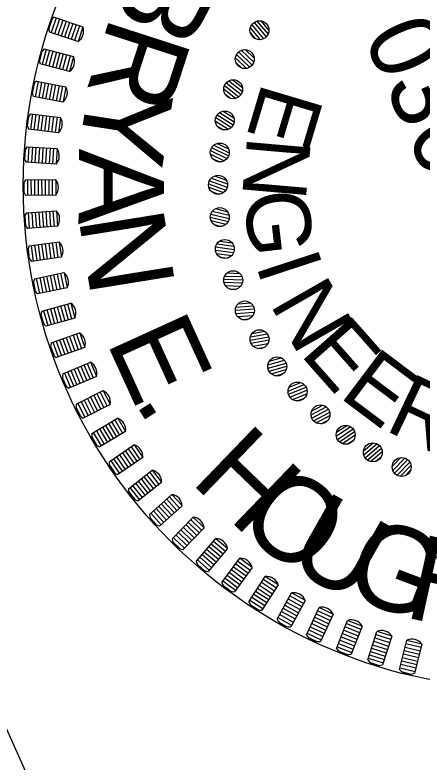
# Model space of a CAD drawing. Extents: x 885268 to 886953, y 552794 to 554777.
# Drawn here: x 886789.1 to 886819.5, y 553213.9 to 553269.8 of the extents above; entities that cross this region are included whole.
import ezdxf

# ---------------------------------------------------------------- set-up
doc = ezdxf.new("R2010")
doc.units = 0
doc.layers.add('Sheet PE Seal Cell', color=7, linetype='Continuous')
doc.layers.add('Sheet Plan CELL', color=7, linetype='Continuous')

msp = doc.modelspace()

# ---------------------------------------------------------------- linework, layer by layer
at = {"layer": 'Sheet PE Seal Cell'}
for p, q in [((886792.129, 553269.585), (886791.758, 553268.483)), ((886791.999, 553269.629), (886794.129, 553268.911)), ((886791.805, 553269.454), (886791.579, 553268.783)), ((886792.38, 553269.5), (886792.009, 553268.398)), ((886792.632, 553269.416), (886792.26, 553268.314)), ((886792.883, 553269.331), (886792.512, 553268.229)), ((886793.135, 553269.246), (886792.763, 553268.144)), ((886793.386, 553269.162), (886793.015, 553268.06)), ((886793.638, 553269.077), (886793.266, 553267.975)), ((886793.889, 553268.992), (886793.518, 553267.89)), ((886806.764, 553269.074), (886807.647, 553268.022)), ((886806.932, 553269.241), (886807.84, 553268.159)), ((886807.153, 553269.345), (886807.981, 553268.358)), ((886807.447, 553269.362), (886808.049, 553268.645)), ((886793.758, 553267.809), (886791.628, 553268.527)), ((886794.136, 553268.894), (886793.774, 553267.819)), ((886806.653, 553268.837), (886807.395, 553267.954)), ((886806.659, 553268.463), (886807.027, 553268.024)), ((886791.066, 553267.076), (886790.885, 553266.392)), ((886791.381, 553267.228), (886791.083, 553266.104)), ((886791.248, 553267.263), (886793.421, 553266.688)), ((886791.637, 553267.16), (886791.34, 553266.036)), ((886791.894, 553267.092), (886791.596, 553265.968)), ((886792.15, 553267.024), (886791.853, 553265.9)), ((886792.407, 553266.957), (886792.109, 553265.832)), ((886792.663, 553266.889), (886792.366, 553265.765)), ((886792.92, 553266.821), (886792.622, 553265.697)), ((886793.176, 553266.753), (886792.879, 553265.629)), ((886805.625, 553266.853), (886806.613, 553265.899)), ((886805.775, 553267.037), (886806.791, 553266.056)), ((886805.984, 553267.163), (886806.911, 553266.269)), ((886806.275, 553267.211), (886806.948, 553266.562)), ((886793.429, 553266.671), (886793.139, 553265.575)), ((886805.54, 553266.606), (886806.37, 553265.805)), ((886805.585, 553266.235), (886805.997, 553265.837)), ((886793.124, 553265.564), (886790.951, 553266.139)), ((886790.486, 553264.655), (886790.35, 553263.959)), ((886790.79, 553264.827), (886790.567, 553263.685)), ((886790.655, 553264.853), (886792.862, 553264.423)), ((886791.05, 553264.776), (886790.828, 553263.635)), ((886791.311, 553264.725), (886791.088, 553263.584)), ((886791.571, 553264.674), (886791.349, 553263.533)), ((886791.832, 553264.624), (886791.609, 553263.482)), ((886792.092, 553264.573), (886791.87, 553263.432)), ((886792.353, 553264.522), (886792.13, 553263.381)), ((886804.725, 553264.526), (886805.807, 553263.68)), ((886804.855, 553264.724), (886805.968, 553263.854)), ((886805.049, 553264.872), (886806.064, 553264.079)), ((886805.334, 553264.949), (886806.071, 553264.374)), ((886792.613, 553264.471), (886792.39, 553263.33)), ((886792.871, 553264.406), (886792.654, 553263.293)), ((886804.666, 553264.272), (886805.575, 553263.562)), ((886792.639, 553263.281), (886790.433, 553263.712)), ((886804.75, 553263.906), (886805.201, 553263.554)), ((886790.359, 553262.392), (886790.213, 553261.238)), ((886790.223, 553262.409), (886792.454, 553262.125)), ((886790.622, 553262.358), (886790.476, 553261.205)), ((886790.886, 553262.325), (886790.739, 553261.171)), ((886791.149, 553262.291), (886791.002, 553261.138)), ((886791.412, 553262.258), (886791.266, 553261.104)), ((886804.181, 553262.328), (886805.379, 553261.579)), ((886804.359, 553262.495), (886805.452, 553261.813)), ((886804.634, 553262.602), (886805.427, 553262.107)), ((886790.067, 553262.2), (886789.978, 553261.497)), ((886791.675, 553262.224), (886791.529, 553261.071)), ((886791.939, 553262.191), (886791.792, 553261.037)), ((886792.202, 553262.157), (886792.055, 553261.004)), ((886792.463, 553262.11), (886792.32, 553260.985)), ((886804.041, 553261.858), (886805.019, 553261.247)), ((886804.072, 553262.117), (886805.238, 553261.389)), ((886792.307, 553260.972), (886790.077, 553261.255)), ((886804.162, 553261.504), (886804.647, 553261.201)), ((886803.921, 553260.059), (886805.079, 553259.495)), ((886804.183, 553260.194), (886805.024, 553259.785)), ((886789.812, 553259.723), (886789.769, 553259.016)), ((886789.954, 553259.942), (886792.198, 553259.806)), ((886790.09, 553259.933), (886790.02, 553258.773)), ((886790.355, 553259.917), (886790.285, 553258.757)), ((886790.62, 553259.901), (886790.55, 553258.741)), ((886790.885, 553259.885), (886790.815, 553258.725)), ((886791.15, 553259.869), (886791.08, 553258.709)), ((886791.415, 553259.853), (886791.345, 553258.693)), ((886791.68, 553259.837), (886791.61, 553258.677)), ((886791.945, 553259.821), (886791.874, 553258.661)), ((886792.209, 553259.791), (886792.14, 553258.659)), ((886803.676, 553259.653), (886804.91, 553259.051)), ((886803.762, 553259.874), (886805.032, 553259.255)), ((886803.671, 553259.392), (886804.708, 553258.887)), ((886803.829, 553259.053), (886804.343, 553258.802)), ((886792.128, 553258.645), (886789.884, 553258.781)), ((886789.721, 553257.234), (886789.725, 553256.526)), ((886789.848, 553257.462), (886792.096, 553257.475)), ((886789.985, 553257.463), (886789.991, 553256.3)), ((886790.25, 553257.464), (886790.257, 553256.301)), ((886790.515, 553257.466), (886790.522, 553256.303)), ((886790.781, 553257.467), (886790.788, 553256.305)), ((886791.046, 553257.469), (886791.053, 553256.306)), ((886791.311, 553257.471), (886791.318, 553256.308)), ((886791.577, 553257.472), (886791.584, 553256.309)), ((886791.842, 553257.474), (886791.849, 553256.311)), ((886792.108, 553257.461), (886792.114, 553256.327)), ((886803.601, 553257.39), (886804.929, 553256.907)), ((886803.74, 553257.591), (886804.951, 553257.151)), ((886803.987, 553257.753), (886804.866, 553257.433)), ((886803.539, 553257.161), (886804.83, 553256.692)), ((886803.561, 553256.902), (886804.645, 553256.508)), ((886792.103, 553256.312), (886789.854, 553256.299)), ((886803.754, 553256.58), (886804.292, 553256.385)), ((886789.906, 553254.981), (886792.148, 553255.142)), ((886790.042, 553254.991), (886790.126, 553253.831)), ((886790.307, 553255.01), (886790.391, 553253.85)), ((886790.572, 553255.029), (886790.655, 553253.869)), ((886790.836, 553255.048), (886790.92, 553253.888)), ((886791.101, 553255.067), (886791.185, 553253.907)), ((886791.366, 553255.086), (886791.449, 553253.926)), ((886791.63, 553255.105), (886791.714, 553253.945)), ((886791.895, 553255.124), (886791.979, 553253.964)), ((886792.161, 553255.129), (886792.242, 553253.998)), ((886803.819, 553255.117), (886805.068, 553254.806)), ((886804.047, 553255.304), (886804.954, 553255.078)), ((886789.794, 553254.745), (886789.845, 553254.038)), ((886803.663, 553254.669), (886804.996, 553254.337)), ((886803.701, 553254.903), (886805.072, 553254.562)), ((886803.713, 553254.413), (886804.832, 553254.134)), ((886792.232, 553253.983), (886789.989, 553253.821)), ((886803.937, 553254.114), (886804.493, 553253.975)), ((886790.128, 553252.509), (886792.355, 553252.818)), ((886791.84, 553252.747), (886792.001, 553251.595)), ((886792.103, 553252.783), (886792.263, 553251.631)), ((886792.368, 553252.805), (886792.524, 553251.682)), ((886804.362, 553252.875), (886805.288, 553252.745)), ((886790.032, 553252.266), (886790.129, 553251.564)), ((886790.263, 553252.528), (886790.424, 553251.376)), ((886790.526, 553252.564), (886790.686, 553251.412)), ((886790.789, 553252.601), (886790.949, 553251.449)), ((886791.052, 553252.637), (886791.212, 553251.485)), ((886791.315, 553252.674), (886791.475, 553251.522)), ((886791.578, 553252.71), (886791.738, 553251.558)), ((886804.047, 553252.203), (886805.407, 553252.013)), ((886804.06, 553252.44), (886805.459, 553252.244)), ((886804.155, 553252.665), (886805.43, 553252.487)), ((886792.515, 553251.666), (886790.288, 553251.357)), ((886804.123, 553251.954), (886805.265, 553251.794)), ((886804.378, 553251.68), (886804.945, 553251.6)), ((886790.513, 553250.057), (886792.714, 553250.513)), ((886792.728, 553250.501), (886792.958, 553249.391)), ((886804.93, 553250.492), (886805.865, 553250.46)), ((886790.647, 553250.085), (886790.883, 553248.946)), ((886790.907, 553250.138), (886791.143, 553249)), ((886791.166, 553250.192), (886791.402, 553249.053)), ((886791.426, 553250.246), (886791.662, 553249.107)), ((886791.686, 553250.3), (886791.922, 553249.161)), ((886791.946, 553250.354), (886792.182, 553249.215)), ((886792.206, 553250.407), (886792.442, 553249.269)), ((886792.466, 553250.461), (886792.702, 553249.323)), ((886804.675, 553250.028), (886806.087, 553249.979)), ((886804.746, 553250.262), (886806.033, 553250.218)), ((886790.433, 553249.808), (886790.577, 553249.115)), ((886792.95, 553249.374), (886790.749, 553248.918)), ((886804.686, 553249.791), (886806.059, 553249.744)), ((886804.788, 553249.551), (886805.941, 553249.511)), ((886805.071, 553249.305), (886805.642, 553249.285)), ((886791.059, 553247.636), (886793.225, 553248.236)), ((886791.446, 553247.743), (886791.757, 553246.622)), ((886791.702, 553247.814), (886792.013, 553246.693)), ((886791.958, 553247.885), (886792.269, 553246.764)), ((886792.214, 553247.956), (886792.524, 553246.835)), ((886792.469, 553248.027), (886792.78, 553246.906)), ((886792.725, 553248.097), (886793.036, 553246.977)), ((886792.981, 553248.168), (886793.291, 553247.048)), ((886793.24, 553248.225), (886793.543, 553247.132)), ((886805.539, 553247.694), (886806.948, 553247.793)), ((886805.584, 553247.934), (886806.869, 553248.024)), ((886805.744, 553248.182), (886806.677, 553248.247)), ((886790.996, 553247.382), (886791.185, 553246.7)), ((886791.191, 553247.672), (886791.501, 553246.552)), ((886805.575, 553247.459), (886806.945, 553247.555)), ((886805.701, 553247.231), (886806.852, 553247.312)), ((886793.536, 553247.115), (886791.369, 553246.515)), ((886806.008, 553247.016), (886806.578, 553247.056)), ((886806.794, 553245.969), (886807.715, 553246.132)), ((886791.764, 553245.256), (886793.886, 553245.998)), ((886792.394, 553245.476), (886792.778, 553244.379)), ((886792.644, 553245.564), (886793.028, 553244.466)), ((886792.895, 553245.652), (886793.279, 553244.554)), ((886793.145, 553245.739), (886793.529, 553244.642)), ((886793.396, 553245.827), (886793.78, 553244.729)), ((886793.646, 553245.914), (886794.03, 553244.817)), ((886793.901, 553245.988), (886794.276, 553244.918)), ((886806.641, 553245.462), (886808.033, 553245.708)), ((886806.662, 553245.706), (886807.93, 553245.93)), ((886806.702, 553245.233), (886808.055, 553245.472)), ((886791.718, 553244.999), (886791.951, 553244.33)), ((886791.893, 553245.301), (886792.277, 553244.203)), ((886792.143, 553245.389), (886792.527, 553244.291)), ((886794.27, 553244.901), (886792.148, 553244.158)), ((886806.851, 553245.019), (886807.987, 553245.22)), ((886807.179, 553244.837), (886807.742, 553244.937)), ((886792.624, 553242.928), (886794.693, 553243.809)), ((886794.709, 553243.8), (886795.153, 553242.757)), ((886807.966, 553243.602), (886809.204, 553243.958)), ((886808.071, 553243.878), (886808.97, 553244.136)), ((886793.483, 553243.293), (886793.938, 553242.224)), ((886793.727, 553243.397), (886794.183, 553242.328)), ((886793.971, 553243.501), (886794.427, 553242.432)), ((886794.215, 553243.605), (886794.671, 553242.536)), ((886794.459, 553243.709), (886794.915, 553242.64)), ((886807.972, 553243.358), (886809.33, 553243.748)), ((886808.056, 553243.136), (886809.376, 553243.515)), ((886808.227, 553242.94), (886809.335, 553243.258)), ((886792.595, 553242.668), (886792.873, 553242.017)), ((886792.75, 553242.982), (886793.206, 553241.912)), ((886792.994, 553243.086), (886793.45, 553242.016)), ((886795.148, 553242.739), (886793.08, 553241.858)), ((886793.239, 553243.189), (886793.694, 553242.12)), ((886808.571, 553242.793), (886809.121, 553242.951)), ((886809.484, 553241.647), (886810.678, 553242.13)), ((886809.558, 553241.932), (886810.425, 553242.283)), ((886793.637, 553240.662), (886795.642, 553241.678)), ((886795.416, 553241.563), (886795.942, 553240.526)), ((886795.659, 553241.67), (886796.172, 553240.658)), ((886809.514, 553241.405), (886810.824, 553241.934)), ((886809.621, 553241.193), (886810.894, 553241.708)), ((886794.469, 553241.083), (886794.995, 553240.046)), ((886794.706, 553241.203), (886795.231, 553240.166)), ((886794.943, 553241.323), (886795.468, 553240.286)), ((886795.179, 553241.443), (886795.705, 553240.406)), ((886809.812, 553241.015), (886810.881, 553241.448)), ((886810.17, 553240.905), (886810.7, 553241.12)), ((886793.759, 553240.724), (886794.285, 553239.686)), ((886793.996, 553240.844), (886794.521, 553239.806)), ((886796.168, 553240.64), (886794.162, 553239.624)), ((886794.233, 553240.964), (886794.758, 553239.926)), ((886811.197, 553239.861), (886812.334, 553240.466)), ((886811.242, 553240.153), (886812.067, 553240.592)), ((886793.625, 553240.401), (886793.945, 553239.769)), ((886811.253, 553239.623), (886812.5, 553240.287)), ((886811.381, 553239.424), (886812.594, 553240.069)), ((886794.797, 553238.468), (886796.731, 553239.614)), ((886796.285, 553239.349), (886796.877, 553238.349)), ((886796.513, 553239.484), (886797.106, 553238.484)), ((886796.749, 553239.607), (886797.327, 553238.632)), ((886811.589, 553239.267), (886812.607, 553239.809)), ((886811.957, 553239.195), (886812.462, 553239.464)), ((886795.371, 553238.808), (886795.964, 553237.808)), ((886795.6, 553238.943), (886796.193, 553237.943)), ((886795.828, 553239.079), (886796.421, 553238.078)), ((886796.056, 553239.214), (886796.649, 553238.214)), ((886813.087, 553238.264), (886814.155, 553238.985)), ((886813.101, 553238.559), (886813.876, 553239.082)), ((886813.168, 553238.033), (886814.339, 553238.824)), ((886794.803, 553238.207), (886795.164, 553237.597)), ((886794.915, 553238.538), (886795.508, 553237.537)), ((886795.143, 553238.673), (886795.736, 553237.672)), ((886797.324, 553238.613), (886795.39, 553237.467)), ((886813.316, 553237.848), (886814.455, 553238.617)), ((886813.54, 553237.714), (886814.496, 553238.359)), ((886813.913, 553237.681), (886814.387, 553238.001)), ((886815.118, 553237.168), (886815.834, 553237.769)), ((886815.135, 553236.873), (886816.121, 553237.702)), ((886796.1, 553236.355), (886797.954, 553237.626)), ((886797.307, 553237.183), (886797.965, 553236.224)), ((886797.526, 553237.333), (886798.183, 553236.374)), ((886797.745, 553237.483), (886798.402, 553236.524)), ((886797.972, 553237.621), (886798.613, 553236.686)), ((886815.239, 553236.652), (886816.321, 553237.561)), ((886815.406, 553236.484), (886816.458, 553237.367)), ((886815.642, 553236.374), (886816.525, 553237.115)), ((886796.432, 553236.583), (886797.089, 553235.624)), ((886796.65, 553236.733), (886797.308, 553235.774)), ((886798.611, 553236.667), (886796.757, 553235.396)), ((886796.869, 553236.883), (886797.527, 553235.924)), ((886797.088, 553237.033), (886797.746, 553236.074)), ((886816.016, 553236.38), (886816.455, 553236.748)), ((886817.268, 553235.995), (886817.918, 553236.668)), ((886817.316, 553235.704), (886818.21, 553236.631)), ((886817.443, 553235.495), (886818.424, 553236.512)), ((886796.122, 553236.095), (886796.523, 553235.511)), ((886796.213, 553236.433), (886796.87, 553235.474)), ((886817.626, 553235.345), (886818.58, 553236.334)), ((886817.873, 553235.26), (886818.674, 553236.09)), ((886797.539, 553234.333), (886799.305, 553235.724)), ((886798.897, 553235.403), (886799.617, 553234.49)), ((886799.106, 553235.567), (886799.825, 553234.654)), ((886799.323, 553235.72), (886800.025, 553234.829)), ((886818.245, 553235.305), (886818.642, 553235.717)), ((886798.272, 553234.91), (886798.992, 553233.997)), ((886798.481, 553235.075), (886799.2, 553234.161)), ((886798.689, 553235.239), (886799.409, 553234.325)), ((886797.647, 553234.418), (886798.366, 553233.504)), ((886797.855, 553234.582), (886798.575, 553233.669)), ((886798.064, 553234.746), (886798.783, 553233.833)), ((886800.025, 553234.811), (886798.259, 553233.42)), ((886797.579, 553234.075), (886798.017, 553233.519)), ((886799.109, 553232.411), (886800.779, 553233.916)), ((886800.591, 553233.746), (886801.369, 553232.882)), ((886800.798, 553233.913), (886801.557, 553233.07)), ((886799.999, 553233.213), (886800.778, 553232.349)), ((886800.196, 553233.391), (886800.975, 553232.527)), ((886800.394, 553233.568), (886801.172, 553232.704)), ((886799.408, 553232.68), (886800.186, 553231.816)), ((886799.605, 553232.858), (886800.383, 553231.994)), ((886799.802, 553233.035), (886800.581, 553232.171)), ((886801.558, 553233.052), (886799.887, 553231.547)), ((886799.166, 553232.156), (886799.64, 553231.63)), ((886799.211, 553232.502), (886799.989, 553231.639)), ((886800.803, 553230.596), (886802.37, 553232.208)), ((886802.388, 553232.207), (886803.201, 553231.416)), ((886801.823, 553231.646), (886802.657, 553230.835)), ((886802.008, 553231.836), (886802.842, 553231.026)), ((886802.193, 553232.026), (886803.027, 553231.216)), ((886801.268, 553231.075), (886802.102, 553230.264)), ((886801.453, 553231.265), (886802.287, 553230.455)), ((886803.203, 553231.398), (886801.636, 553229.786)), ((886801.638, 553231.456), (886802.472, 553230.645)), ((886800.898, 553230.695), (886801.732, 553229.884)), ((886801.083, 553230.885), (886801.917, 553230.074)), ((886802.612, 553228.898), (886804.069, 553230.61)), ((886803.905, 553230.417), (886804.791, 553229.663)), ((886804.088, 553230.609), (886804.952, 553229.874)), ((886800.876, 553230.346), (886801.384, 553229.852)), ((886803.389, 553229.81), (886804.275, 553229.057)), ((886804.955, 553229.856), (886803.498, 553228.144)), ((886803.561, 553230.012), (886804.447, 553229.259)), ((886803.733, 553230.214), (886804.619, 553229.461)), ((886803.045, 553229.406), (886803.931, 553228.653)), ((886803.217, 553229.608), (886804.103, 553228.855)), ((886802.701, 553229.002), (886803.587, 553228.248)), ((886802.873, 553229.204), (886803.759, 553228.45)), ((886804.53, 553227.323), (886805.871, 553229.127)), ((886805.562, 553228.71), (886806.495, 553228.017)), ((886805.72, 553228.923), (886806.653, 553228.23)), ((886805.89, 553229.128), (886806.8, 553228.452)), ((886802.702, 553228.653), (886803.242, 553228.194)), ((886805.245, 553228.284), (886806.178, 553227.591)), ((886805.403, 553228.497), (886806.337, 553227.804)), ((886806.805, 553228.434), (886805.464, 553226.629)), ((886804.77, 553227.646), (886805.704, 553226.952)), ((886804.929, 553227.859), (886805.862, 553227.165)), ((886805.087, 553228.071), (886806.02, 553227.378)), ((886806.548, 553225.878), (886807.767, 553227.767)), ((886807.785, 553227.769), (886808.738, 553227.154)), ((886804.612, 553227.433), (886805.545, 553226.739)), ((886804.636, 553227.084), (886805.205, 553226.662)), ((886807.342, 553227.108), (886808.319, 553226.477)), ((886807.486, 553227.331), (886808.463, 553226.7)), ((886808.744, 553227.136), (886807.525, 553225.247)), ((886807.629, 553227.554), (886808.607, 553226.923)), ((886807.054, 553226.662), (886808.031, 553226.031)), ((886807.198, 553226.885), (886808.175, 553226.254)), ((886808.657, 553224.569), (886809.748, 553226.535)), ((886809.767, 553226.538), (886810.758, 553225.988)), ((886806.623, 553225.993), (886807.6, 553225.362)), ((886806.766, 553226.216), (886807.744, 553225.585)), ((886806.91, 553226.439), (886807.887, 553225.808)), ((886809.496, 553226.081), (886810.513, 553225.517)), ((886809.625, 553226.313), (886810.642, 553225.749)), ((886810.765, 553225.97), (886809.674, 553224.005)), ((886806.67, 553225.647), (886807.265, 553225.263)), ((886809.11, 553225.385), (886810.127, 553224.821)), ((886809.239, 553225.617), (886810.256, 553225.053)), ((886809.368, 553225.849), (886810.384, 553225.285)), ((886810.848, 553223.403), (886811.807, 553225.436)), ((886811.825, 553225.441), (886812.851, 553224.957)), ((886808.853, 553224.921), (886809.869, 553224.356)), ((886808.981, 553225.153), (886809.998, 553224.588)), ((886811.586, 553224.967), (886812.637, 553224.471)), ((886811.699, 553225.207), (886812.751, 553224.711)), ((886812.859, 553224.94), (886811.9, 553222.907)), ((886808.724, 553224.689), (886809.741, 553224.124)), ((886808.794, 553224.347), (886809.413, 553224.003)), ((886811.246, 553224.247), (886812.298, 553223.751)), ((886811.359, 553224.487), (886812.411, 553223.991)), ((886811.472, 553224.727), (886812.524, 553224.231)), ((886813.111, 553222.384), (886813.934, 553224.476)), ((886813.841, 553224.24), (886814.923, 553223.815)), ((886813.951, 553224.482), (886815.007, 553224.067)), ((886811.02, 553223.767), (886812.072, 553223.271)), ((886811.133, 553224.007), (886812.185, 553223.511)), ((886813.647, 553223.746), (886814.729, 553223.321)), ((886813.744, 553223.993), (886814.826, 553223.568)), ((886815.016, 553224.051), (886814.194, 553221.959)), ((886815.437, 553221.517), (886816.119, 553223.659)), ((886816.137, 553223.666), (886817.217, 553223.322)), ((886810.907, 553223.527), (886811.958, 553223.031)), ((886810.999, 553223.19), (886811.64, 553222.888)), ((886813.453, 553223.252), (886814.535, 553222.827)), ((886813.55, 553223.499), (886814.632, 553223.074)), ((886815.962, 553223.164), (886817.07, 553222.812)), ((886816.042, 553223.417), (886817.15, 553223.064)), ((886817.227, 553223.306), (886816.545, 553221.164)), ((886813.259, 553222.758), (886814.341, 553222.333)), ((886813.356, 553223.005), (886814.438, 553222.58)), ((886815.801, 553222.659), (886816.909, 553222.306)), ((886815.881, 553222.912), (886816.989, 553222.559)), ((886817.815, 553220.805), (886818.354, 553222.988)), ((886818.293, 553222.742), (886819.422, 553222.463)), ((886818.371, 553222.996), (886819.472, 553222.724)), ((886819.483, 553222.709), (886818.944, 553220.527)), ((886813.162, 553222.511), (886814.244, 553222.086)), ((886813.276, 553222.181), (886813.935, 553221.922)), ((886815.64, 553222.153), (886816.748, 553221.8)), ((886815.72, 553222.406), (886816.828, 553222.053)), ((886818.102, 553221.969), (886819.231, 553221.69)), ((886818.166, 553222.226), (886819.295, 553221.948)), ((886818.229, 553222.484), (886819.358, 553222.205)), ((886815.479, 553221.647), (886816.587, 553221.295)), ((886815.559, 553221.9), (886816.667, 553221.547)), ((886817.975, 553221.454), (886819.104, 553221.175)), ((886818.039, 553221.711), (886819.167, 553221.432)), ((886815.615, 553221.326), (886816.29, 553221.111)), ((886817.848, 553220.938), (886818.977, 553220.66)), ((886817.911, 553221.196), (886819.04, 553220.917)), ((886818.005, 553220.626), (886818.692, 553220.456))]:
    msp.add_line(p, q, dxfattribs=at)
for centre, radius in [((886827.4, 553257.054), 37.726), ((886807.34, 553268.661), 0.709), ((886806.241, 553266.503), 0.709), ((886805.374, 553264.242), 0.709), ((886804.748, 553261.902), 0.709), ((886804.37, 553259.51), 0.709), ((886804.244, 553257.092), 0.709), ((886804.372, 553254.674), 0.709), ((886804.751, 553252.282), 0.709), ((886805.379, 553249.943), 0.709), ((886806.248, 553247.683), 0.709), ((886807.348, 553245.526), 0.709), ((886808.667, 553243.495), 0.709), ((886810.192, 553241.614), 0.709), ((886811.905, 553239.902), 0.709), ((886813.787, 553238.379), 0.709), ((886815.818, 553237.06), 0.709), ((886817.976, 553235.962), 0.709)]:
    msp.add_circle(centre, radius, dxfattribs=at)
for centre, radius, start, end in [((886792.537, 553268.834), 0.96, 124.1168, 198.6578), ((886793.275, 553268.585), 0.914, 301.8906, 20.884), ((886791.838, 553266.506), 0.96, 127.9063, 202.4473), ((886792.591, 553266.306), 0.914, 305.68, 24.6735), ((886791.294, 553264.136), 0.96, 131.6958, 206.2367), ((886792.058, 553263.987), 0.914, 309.4695, 28.463), ((886790.908, 553261.736), 0.96, 135.4852, 210.0262), ((886791.68, 553261.638), 0.914, 313.259, 32.2525), ((886790.681, 553259.315), 0.96, 139.2747, 213.8157), ((886791.459, 553259.268), 0.914, 317.0485, 36.0419), ((886790.615, 553256.885), 0.96, 143.0642, 217.6052), ((886791.394, 553256.89), 0.914, 320.8379, 39.8314), ((886790.71, 553254.456), 0.96, 146.8537, 221.3946), ((886791.486, 553254.512), 0.914, 324.6274, 43.6209), ((886791.736, 553252.145), 0.914, 328.4169, 47.4104), ((886790.965, 553252.038), 0.96, 150.6431, 225.1841), ((886792.141, 553249.8), 0.914, 332.2063, 51.1998), ((886791.379, 553249.642), 0.96, 154.4326, 228.9736), ((886792.701, 553247.487), 0.914, 335.9958, 54.9893), ((886791.95, 553247.279), 0.96, 158.2221, 232.763), ((886793.412, 553245.216), 0.914, 339.7853, 58.7788), ((886792.677, 553244.959), 0.96, 162.0116, 236.5525), ((886794.271, 553242.997), 0.914, 343.5748, 62.5683), ((886793.555, 553242.692), 0.96, 165.801, 240.342), ((886795.276, 553240.84), 0.914, 347.3642, 66.3577), ((886794.581, 553240.488), 0.96, 169.5905, 244.1315), ((886796.421, 553238.754), 0.914, 351.1537, 70.1472), ((886795.751, 553238.357), 0.96, 173.38, 247.9209), ((886797.701, 553236.748), 0.914, 354.9432, 73.9367), ((886797.059, 553236.308), 0.96, 177.1694, 251.7104), ((886799.111, 553234.831), 0.914, 358.7327, 77.7262), ((886798.499, 553234.349), 0.96, 180.9589, 255.4999), ((886800.644, 553233.011), 0.914, 2.5221, 81.5156), ((886800.066, 553232.49), 0.96, 184.7484, 259.2894), ((886802.295, 553231.297), 0.914, 6.3116, 85.3051), ((886801.752, 553230.739), 0.96, 188.5379, 263.0788), ((886804.055, 553229.696), 0.914, 10.1011, 89.0946), ((886803.55, 553229.103), 0.96, 192.3273, 266.8683), ((886805.917, 553228.214), 0.914, 13.8906, 92.884), ((886807.873, 553226.859), 0.914, 17.68, 96.6735), ((886805.453, 553227.589), 0.96, 196.1168, 270.6578), ((886809.914, 553225.636), 0.914, 21.4695, 100.463), ((886807.451, 553226.204), 0.96, 199.9063, 274.4473), ((886812.032, 553224.55), 0.914, 25.259, 104.2525), ((886809.537, 553224.955), 0.96, 203.6958, 278.2367), ((886814.217, 553223.607), 0.914, 29.0485, 108.0419), ((886816.459, 553222.81), 0.914, 32.8379, 111.8314), ((886811.7, 553223.846), 0.96, 207.4852, 282.0262), ((886818.749, 553222.164), 0.914, 36.6274, 115.6209), ((886813.932, 553222.882), 0.96, 211.2747, 285.8157), ((886816.223, 553222.068), 0.96, 215.0642, 289.6052), ((886818.563, 553221.408), 0.96, 218.8537, 293.3946)]:
    msp.add_arc(centre, radius, start, end, dxfattribs=at)
at = {"layer": 'Sheet Plan CELL'}
msp.add_lwpolyline([(886862.251, 553327.122), (886902.932, 553235.771), (886800.162, 553190.005), (886759.481, 553281.356)], close=True, dxfattribs=at)

# ---------------------------------------------------------------- texts
at = {"layer": 'Sheet PE Seal Cell'}
for s, height, rotation, p in [('B', 6.368, 242.2556, (886798.815, 553274.866)), ('036853', 5.307, 294.0189, (886815.051, 553268.206)), ('R', 6.368, 252.0537, (886796.246, 553269.861)), ('E', 4.776, 253.3737, (886807.591, 553264.878)), ('Y', 6.368, 261.1748, (886794.617, 553264.764)), ('N', 4.776, 264.9866, (886806.438, 553260.82)), ('A', 6.368, 269.5405, (886793.849, 553259.795)), ('G', 4.776, 276.5995, (886806.128, 553256.444)), ('N', 6.368, 279.1792, (886793.794, 553254.622)), ('I', 4.776, 288.2124, (886807.041, 553251.126)), ('N', 4.776, 299.8253, (886808.066, 553248.19)), ('E', 6.368, 294.5084, (886795.845, 553245.389)), ('E', 4.776, 311.4382, (886810.311, 553244.421)), ('E', 4.776, 323.0511, (886813.213, 553241.245)), ('R', 4.776, 334.664, (886816.617, 553238.754)), ('.', 6.368, 303.2088, (886797.913, 553240.856)), ('H', 6.368, 316.0522, (886802.086, 553234.88)), ('O', 6.368, 323.0954, (886805.45, 553231.477)), ('U', 6.368, 330.5529, (886809.175, 553228.699)), ('G', 6.368, 339.2533, (886813.374, 553226.546)), ('H', 6.368, 347.5393, (886818.037, 553224.754))]:
    msp.add_text(s, height=height, rotation=rotation, dxfattribs=at).set_placement(p)

doc.saveas('drawing.dxf')
